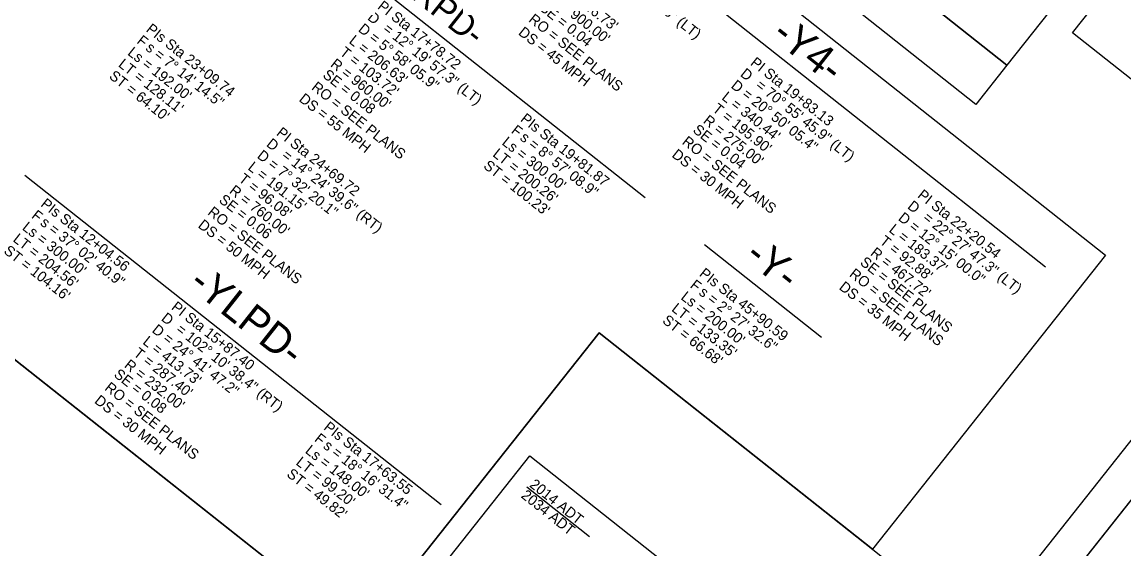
# Model space of a CAD drawing. Extents: x 1771636 to 1784627, y 798645 to 819978.
# Drawn here: x 1783314 to 1784052, y 812169 to 812522 of the extents above; entities that cross this region are included whole.
import ezdxf

# ---------------------------------------------------------------- set-up
doc = ezdxf.new("R2010")
doc.units = 0
for name, color, linetype in [('Exist Hydro Stream Flow Arrow CELL', 7, 'Continuous'), ('Exist Other Culture Well CELL', 7, 'Continuous'), ('Exist Structure Minor Footbridge', 7, 'Continuous'), ('Exist Utilities Power Joint Use Telephone CELL', 7, 'Continuous'), ('Exist Utilities Sanitary Sewer Manhole CELL', 7, 'Continuous'), ('Exist Utilities Telephone Pole CELL', 7, 'Continuous'), ('Exist Utilities Water Fire Hydrant CELL', 7, 'Continuous'), ('Exist Vegetation Woods Line', 7, 'Continuous')]:
    doc.layers.add(name, color=color, linetype=linetype)

msp = doc.modelspace()

# ---------------------------------------------------------------- linework, layer by layer
at = {"layer": 'Exist Hydro Stream Flow Arrow CELL'}
msp.add_lwpolyline([(1784297.88, 812505.92), (1781710.58, 814554.31), (1780665.28, 813234), (1783252.58, 811185.61)], close=True, dxfattribs=at)
at = {"layer": 'Exist Other Culture Well CELL'}
msp.add_lwpolyline([(1784457.99, 812708.16), (1781817.38, 814798.76), (1780451.82, 813073.93), (1783092.43, 810983.33)], close=True, dxfattribs=at)
at = {"layer": 'Exist Structure Minor Footbridge'}
msp.add_line((1783652.05, 812210.62), (1783694.23, 812177.22), dxfattribs=at)
msp.add_lwpolyline([(1783481.26, 812012.88), (1783654.22, 812231.34), (1783891.37, 812043.59), (1783718.41, 811825.12)], close=True, dxfattribs=at)
at = {"layer": 'Exist Utilities Power Joint Use Telephone CELL'}
for points in [[(1781915.64, 814370.28), (1784267.72, 812508.11), (1783243.53, 811214.46), (1780891.44, 813076.63)], [(1784087.57, 812602.84), (1784166.01, 812540.74), (1784096.18, 812452.53), (1784017.74, 812514.64)]]:
    msp.add_lwpolyline(points, close=True, dxfattribs=at)
at = {"layer": 'Exist Utilities Telephone Pole CELL'}
msp.add_lwpolyline([(1783384.75, 813185.41), (1782922.68, 812601.78), (1782968.4, 812565.53), (1783541.01, 812112.27), (1783700.51, 812313.71), (1783949.29, 812116.75), (1783784.11, 811908.02), (1783320.21, 811324), (1783286.6, 811356.67), (1783146.91, 811467.26), (1783125.11, 811467.64), (1783094.07, 811428.44), (1782948.68, 811547.66), (1782956.1, 811557.03), (1782756.79, 811714.83), (1782728.22, 811696.01), (1782447.03, 811920.16), (1782412.5, 811881.47), (1782072.85, 812146.5), (1782110.35, 812188.55), (1781507.48, 812669.12)], dxfattribs=at)
at = {"layer": 'Exist Utilities Water Fire Hydrant CELL'}
for p, q in [((1783468.73, 812612.3), (1783731.47, 812404.29)), ((1783698.69, 812595.95), (1783999.5, 812357.8)), ((1783315.91, 812419.27), (1783594.68, 812198.57)), ((1783771.15, 812372.87), (1783849.62, 812310.75))]:
    msp.add_line(p, q, dxfattribs=at)
at = {"layer": 'Exist Vegetation Woods Line'}
for points in [[(1783405.84, 813177.35), (1784088.01, 812637.27), (1783973.7, 812492.9), (1783291.54, 813032.98)], [(1783291.54, 813032.98), (1783973.7, 812492.9), (1783952.93, 812466.66), (1783270.77, 813006.74)], [(1783243.56, 812995.92), (1784039.66, 812365.64), (1783883.72, 812168.66), (1783700.51, 812313.71), (1783541.01, 812112.27), (1782928.12, 812597.5)]]:
    msp.add_lwpolyline(points, close=True, dxfattribs=at)

# ---------------------------------------------------------------- texts
at = {"layer": 'Exist Structure Minor Footbridge'}
for s, p in [(' 2014 ADT', (1783651.43, 812212.56)), (' 2034 ADT', (1783645.74, 812205.36))]:
    msp.add_text(s, height=7, rotation=321.63116, dxfattribs=at).set_placement(p)
at = {"layer": 'Exist Utilities Sanitary Sewer Manhole CELL'}
for s, rotation, p in [('= 18%%d 31\' 10.6" (LT)', 321.58299, (1783702.05, 812560.28)), ("T = 146.73'", 321.58299, (1783673.16, 812544.53)), ("R = 900.00'", 321.58299, (1783666.94, 812536.7)), ('PI Sta 17+78.72', 321.63086, (1783551.68, 812531.36)), ('SE = 0.04', 321.62433, (1783659.99, 812530.48)), ('D', 321.63086, (1783544.94, 812523.94)), ('RO = SEE PLANS', 321.62433, (1783652.81, 812522.56)), ('PIs Sta 23+09.74', 321.63086, (1783396.64, 812516.04)), ('D = 5%%d 58\' 05.9"', 321.63086, (1783538.73, 812516.1)), ('= 12%%d 19\' 57.3" (LT)', 321.63086, (1783555.2, 812516.2)), ('DS = 45 MPH', 321.71881, (1783645.96, 812513.89)), ('F', 321.63086, (1783390.43, 812508.2)), ("L = 206.63'", 321.63086, (1783532.52, 812508.26)), ("Ls = 192.00'", 321.63086, (1783384.23, 812500.36)), ('s = 7%%d 14\' 14.5"', 321.63086, (1783396.33, 812503.54)), ("T = 103.72'", 321.63086, (1783526.32, 812500.42)), ("LT = 128.11'", 321.63086, (1783378.02, 812492.52)), ("R = 960.00'", 321.63086, (1783520.11, 812492.58)), ('PI Sta 19+83.13', 321.58299, (1783801.36, 812493.53)), ('SE = 0.08', 321.62433, (1783514.88, 812485.41)), ('D', 321.58299, (1783794.62, 812486.12)), ("ST = 64.10'", 321.63086, (1783371.81, 812484.68)), ('RO = SEE PLANS', 321.62433, (1783507.38, 812477.12)), ('D = 20%%d 50\' 05.4"', 321.58299, (1783788.4, 812478.28)), ('= 70%%d 55\' 45.9" (LT)', 321.58299, (1783804.87, 812478.36)), ('DS = 55 MPH', 321.71881, (1783499.02, 812469.3)), ("L = 340.44'", 321.58299, (1783782.19, 812470.45)), ("T = 195.90'", 321.58299, (1783775.97, 812462.61)), ('PIs Sta 19+81.87', 321.63086, (1783647.38, 812455.93)), ("R = 275.00'", 321.58299, (1783769.76, 812454.78)), ('F', 321.63086, (1783641.17, 812448.09)), ('SE = 0.04', 321.62433, (1783762.81, 812448.56)), ('PI Sta 24+69.72', 321.63086, (1783483.93, 812446.6)), ("Ls = 300.00'", 321.63086, (1783634.97, 812440.25)), ('s = 8%%d 57\' 08.9"', 321.63086, (1783647.06, 812443.43)), ('RO = SEE PLANS', 321.62433, (1783755.63, 812440.64)), ('D', 321.63086, (1783477.19, 812439.17)), ("LT = 200.26'", 321.63086, (1783628.76, 812432.41)), ('D = 7%%d 32\' 20.1"', 321.63086, (1783470.98, 812431.33)), ('= 14%%d 24\' 39.6" (RT)', 321.63086, (1783487.45, 812431.43)), ('DS = 30 MPH', 321.71881, (1783748.77, 812431.97)), ("L = 191.15'", 321.63086, (1783464.78, 812423.49)), ("ST = 100.23'", 321.63086, (1783622.55, 812424.57)), ("T = 96.08'", 321.63086, (1783458.57, 812415.65)), ("R = 760.00'", 321.63086, (1783452.36, 812407.81)), ('PI Sta 22+20.54', 321.58299, (1783913.34, 812404.87)), ('PIs Sta 12+04.56', 321.69485, (1783326.05, 812398.95)), ('SE = 0.06', 321.62433, (1783445.38, 812401.71)), ('D', 321.58299, (1783906.6, 812397.46)), ('F', 321.69485, (1783319.85, 812391.1)), ('RO = SEE PLANS', 321.62433, (1783437.87, 812393.42)), ('D = 12%%d 15\' 00.0"', 321.58299, (1783900.39, 812389.62)), ('= 22%%d 27\' 47.3" (LT)', 321.58299, (1783916.85, 812389.7)), ("Ls = 300.00'", 321.69485, (1783313.65, 812383.25)), ('s = 37%%d 02\' 40.9"', 321.69485, (1783325.75, 812386.44)), ('DS = 50 MPH', 321.71881, (1783431.39, 812384.77)), ("L = 183.37'", 321.58299, (1783894.17, 812381.79)), ("LT = 204.56'", 321.69485, (1783307.45, 812375.4)), ("T = 92.88'", 321.58299, (1783887.96, 812373.95)), ("ST = 104.16'", 321.69485, (1783301.26, 812367.56)), ("R = 467.72'", 321.58299, (1783881.75, 812366.12)), ('SE = SEE PLANS', 321.62433, (1783874.8, 812359.9)), ('PIs Sta 45+90.59', 321.70041, (1783767.18, 812352.3)), ('RO = SEE PLANS', 321.62433, (1783867.62, 812351.98)), ('F', 321.70041, (1783760.98, 812344.45)), ("Ls = 200.00'", 321.70041, (1783754.78, 812336.6)), ('s = 2%%d 27\' 32.6"', 321.70041, (1783766.88, 812339.79)), ('DS = 35 MPH', 321.71881, (1783860.76, 812343.31)), ('PI Sta 15+87.40', 321.69485, (1783413.49, 812329.84)), ('D', 321.69485, (1783406.76, 812322.41)), ("LT = 133.35'", 321.70041, (1783748.58, 812328.76)), ('D = 24%%d 41\' 47.2"', 321.69485, (1783400.57, 812314.56)), ("ST = 66.68'", 321.70041, (1783742.39, 812320.91)), ('= 102%%d 10\' 38.4" (RT)', 321.69485, (1783416.57, 812314.81)), ("L = 413.73'", 321.69485, (1783394.37, 812306.71)), ("T = 287.40'", 321.69485, (1783388.17, 812298.87)), ("R = 232.00'", 321.69485, (1783381.97, 812291.02)), ('SE = 0.08', 321.62433, (1783375.02, 812284.8)), ('RO = SEE PLANS', 321.62433, (1783368.88, 812275.83)), ('DS = 30 MPH', 321.71881, (1783362.02, 812267.16)), ('PIs Sta 17+63.55', 321.69485, (1783515.57, 812249.4)), ('F', 321.69485, (1783509.37, 812241.56)), ("Ls = 148.00'", 321.69485, (1783503.17, 812233.71)), ('s = 18%%d 16\' 31.4"', 321.69485, (1783515.27, 812236.9)), ("LT = 99.20'", 321.69485, (1783496.97, 812225.86)), ("ST = 49.82'", 321.69485, (1783490.77, 812218.02))]:
    msp.add_text(s, height=7, rotation=rotation, dxfattribs=at).set_placement(p)
at = {"layer": 'Exist Utilities Water Fire Hydrant CELL'}
for s, height, p in [('-YRPD-', 16.4, (1783556.82, 812552.03)), ('-Y4-', 20, (1783815.22, 812511.43)), ('-Y-', 20, (1783797.19, 812363.27)), ('-YLPD-', 20, (1783424.67, 812344.71))]:
    msp.add_text(s, height=height, rotation=321.63093, dxfattribs=at).set_placement(p)

doc.saveas('drawing.dxf')
